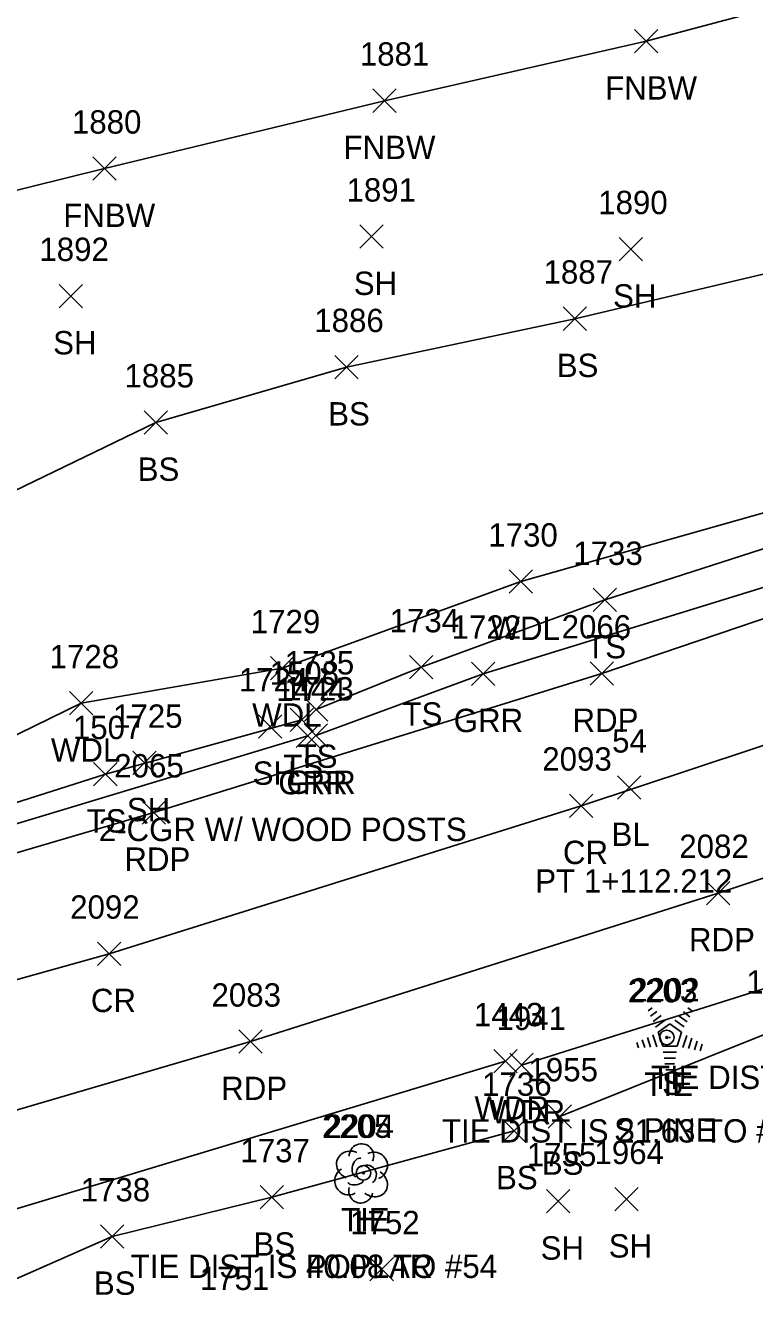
# Model space of a CAD drawing. Extents: x 1526508 to 1531550, y 369926 to 373082.
# Drawn here: x 1531169.1 to 1531231.6, y 370143.1 to 370252.3 of the extents above; entities that cross this region are included whole.
import ezdxf

# ---------------------------------------------------------------- set-up
doc = ezdxf.new("R2010")
doc.units = 0
for name, color, linetype in [('C_A', 7, 'Continuous'), ('C_C', 7, 'Continuous'), ('C_I', 7, 'Continuous'), ('C_TIC', 7, 'Continuous'), ('CBP', 7, 'Continuous'), ('L_A', 7, 'Continuous'), ('L_C', 7, 'Continuous'), ('L_I', 7, 'Continuous'), ('L_TIC', 7, 'Continuous'), ('LAWA', 7, 'Continuous'), ('LELB', 7, 'Continuous'), ('LFNC', 7, 'Continuous'), ('LTC', 7, 'Continuous'), ('LTD', 7, 'Continuous'), ('P_A', 7, 'Continuous'), ('P_I', 7, 'Continuous'), ('P_TIC', 7, 'Continuous'), ('PET', 7, 'Continuous'), ('PRC', 7, 'Continuous'), ('R_A', 7, 'Continuous'), ('R_C', 7, 'Continuous'), ('R_I', 7, 'Continuous'), ('R_TIC', 7, 'Continuous'), ('RGR', 7, 'Continuous')]:
    doc.layers.add(name, color=color, linetype=linetype)

msp = doc.modelspace()

# ---------------------------------------------------------------- linework, layer by layer
at = {"layer": 'C_TIC'}
for points in [[(1531219.82, 370186.04), (1531221.82, 370188.04)], [(1531221.82, 370186.04), (1531219.82, 370188.04)]]:
    msp.add_lwpolyline(points, dxfattribs=at)
at = {"layer": 'CBP'}
for centre, radius in [((1531224.04, 370165.64), 0.625), ((1531224.04, 370165.64), 0.0833), ((1531198.07, 370154.04), 0.625), ((1531198.07, 370154.04), 0.0833)]:
    msp.add_circle(centre, radius, dxfattribs=at)
at = {"layer": 'L_TIC'}
for points in [[(1531221.28, 370249.96), (1531223.28, 370251.96)], [(1531223.28, 370249.96), (1531221.28, 370251.96)], [(1531198.88, 370244.87), (1531200.88, 370246.87)], [(1531200.88, 370244.87), (1531198.88, 370246.87)], [(1531174.89, 370239.05), (1531176.89, 370241.05)], [(1531176.89, 370239.05), (1531174.89, 370241.05)], [(1531197.75, 370233.23), (1531199.75, 370235.23)], [(1531199.75, 370233.23), (1531197.75, 370235.23)], [(1531219.95, 370232.15), (1531221.95, 370234.15)], [(1531221.95, 370232.15), (1531219.95, 370234.15)], [(1531172.01, 370228.14), (1531174.01, 370230.14)], [(1531174.01, 370228.14), (1531172.01, 370230.14)], [(1531215.18, 370226.2), (1531217.18, 370228.2)], [(1531217.18, 370226.2), (1531215.18, 370228.2)], [(1531195.61, 370222.05), (1531197.61, 370224.05)], [(1531197.61, 370222.05), (1531195.61, 370224.05)], [(1531179.3, 370217.31), (1531181.3, 370219.31)], [(1531181.3, 370217.31), (1531179.3, 370219.31)], [(1531210.54, 370203.68), (1531212.54, 370205.68)], [(1531212.54, 370203.68), (1531210.54, 370205.68)], [(1531217.73, 370202.11), (1531219.73, 370204.11)], [(1531219.73, 370202.11), (1531217.73, 370204.11)], [(1531190.12, 370196.26), (1531192.12, 370198.26)], [(1531192.12, 370196.26), (1531190.12, 370198.26)], [(1531202, 370196.34), (1531204, 370198.34)], [(1531204, 370196.34), (1531202, 370198.34)], [(1531172.89, 370193.26), (1531174.89, 370195.26)], [(1531174.89, 370193.26), (1531172.89, 370195.26)], [(1531193.02, 370192.73), (1531195.02, 370194.73)], [(1531195.02, 370192.73), (1531193.02, 370194.73)], [(1531189.09, 370191.28), (1531191.09, 370193.28)], [(1531191.09, 370191.28), (1531189.09, 370193.28)], [(1531191.8, 370191.85), (1531193.8, 370193.85)], [(1531193.8, 370191.85), (1531191.8, 370193.85)], [(1531178.32, 370188.16), (1531180.32, 370190.16)], [(1531180.32, 370188.16), (1531178.32, 370190.16)], [(1531174.97, 370187.19), (1531176.97, 370189.19)], [(1531176.97, 370187.19), (1531174.97, 370189.19)], [(1531209.22, 370162.6), (1531211.22, 370164.6)], [(1531211.22, 370162.6), (1531209.22, 370164.6)], [(1531210.59, 370162.28), (1531212.59, 370164.28)], [(1531212.59, 370162.28), (1531210.59, 370164.28)], [(1531213.89, 370157.88), (1531215.89, 370159.88)], [(1531215.89, 370157.88), (1531213.89, 370159.88)], [(1531209.97, 370156.64), (1531211.97, 370158.64)], [(1531211.97, 370156.64), (1531209.97, 370158.64)], [(1531189.22, 370150.95), (1531191.22, 370152.95)], [(1531191.22, 370150.95), (1531189.22, 370152.95)], [(1531219.59, 370150.79), (1531221.59, 370152.79)], [(1531221.59, 370150.79), (1531219.59, 370152.79)], [(1531213.75, 370150.61), (1531215.75, 370152.61)], [(1531215.75, 370150.61), (1531213.75, 370152.61)], [(1531175.55, 370147.6), (1531177.55, 370149.6)], [(1531177.55, 370147.6), (1531175.55, 370149.6)], [(1531198.63, 370144.79), (1531200.63, 370146.79)], [(1531200.63, 370144.79), (1531198.63, 370146.79)]]:
    msp.add_lwpolyline(points, dxfattribs=at)
at = {"layer": 'LAWA'}
for points in [[(1531211.59, 370163.28), (1531236.15, 370171.01), (1531264.86, 370180.38), (1531296.6, 370192.07), (1531327.62, 370201.99), (1531350.93, 370208.46), (1531364.52, 370214)], [(1531159.07, 370187.01), (1531173.89, 370194.26), (1531191.12, 370197.26), (1531211.54, 370204.68), (1531235.67, 370211.51)], [(1531110.36, 370111.61), (1531088.81, 370117.3), (1531064.64, 370118.26), (1531064.75, 370123.38), (1531085.74, 370129.03), (1531112.09, 370135.21), (1531155.65, 370147.14), (1531210.22, 370163.6)]]:
    msp.add_lwpolyline(points, dxfattribs=at)
at = {"layer": 'LELB'}
for points in [[(1531144.65, 370206.06), (1531164.57, 370210.72), (1531180.3, 370218.31), (1531196.61, 370223.05), (1531216.18, 370227.2), (1531246.26, 370234.32), (1531259.5, 370237.9), (1531291.92, 370247.44), (1531321.67, 370253.97), (1531341.88, 370260.29), (1531377.42, 370272.37), (1531403.24, 370281.83), (1531425.1, 370287.02), (1531443.59, 370293.1), (1531470.33, 370300.31), (1531494.61, 370309.28), (1531517.9, 370316.82)], [(1531236.29, 370208.78), (1531218.73, 370203.11), (1531203, 370197.34), (1531194.02, 370193.73)], [(1531052, 370157.05), (1531071.33, 370161.04), (1531088.5, 370164.53), (1531103.99, 370168.65), (1531126.82, 370174.37), (1531147.94, 370179.24), (1531175.97, 370188.19), (1531192.8, 370192.85)], [(1531214.89, 370158.88), (1531233.6, 370166.39), (1531254.7, 370173.47), (1531274.83, 370179.73), (1531289.17, 370185.62), (1531304.59, 370187.71)], [(1531210.97, 370157.64), (1531190.22, 370151.95), (1531176.55, 370148.6), (1531161.06, 370141.76), (1531149.58, 370137.75), (1531135.28, 370131.25)]]:
    msp.add_lwpolyline(points, dxfattribs=at)
at = {"layer": 'LFNC'}
msp.add_lwpolyline([(1531134.08, 370228.63), (1531150.19, 370233.69), (1531175.89, 370240.05), (1531199.88, 370245.87), (1531222.28, 370250.96), (1531238.05, 370255.18), (1531253.57, 370259.14), (1531283.27, 370267), (1531318.04, 370276.03), (1531340.6, 370281.65), (1531362.15, 370285.77), (1531399.51, 370294.39), (1531422.47, 370298.84)], dxfattribs=at)
at = {"layer": 'LTC'}
for p, q in [((1531222.45, 370167.93), (1531222.8, 370168.19)), ((1531225.85, 370168.17), (1531226.27, 370167.87)), ((1531222.66, 370167.46), (1531223.19, 370167.85)), ((1531222.87, 370167), (1531223.57, 370167.51)), ((1531223.08, 370166.53), (1531223.95, 370167.17)), ((1531224.73, 370167.13), (1531225.54, 370166.54)), ((1531225.1, 370167.47), (1531225.78, 370166.98)), ((1531225.47, 370167.82), (1531226.02, 370167.42)), ((1531222.85, 370165.86), (1531223.18, 370164.84)), ((1531223.3, 370166.08), (1531224.31, 370166.81)), ((1531223.3, 370166.08), (1531223.69, 370164.88)), ((1531224.31, 370166.81), (1531225.31, 370166.09)), ((1531225.31, 370166.09), (1531224.92, 370164.88)), ((1531221.48, 370165.21), (1531221.63, 370164.74)), ((1531221.94, 370165.43), (1531222.15, 370164.77)), ((1531222.39, 370165.64), (1531222.66, 370164.81)), ((1531224.92, 370164.88), (1531223.69, 370164.88)), ((1531225.75, 370165.82), (1531225.41, 370164.78)), ((1531226.19, 370165.57), (1531225.9, 370164.68)), ((1531226.64, 370165.32), (1531226.4, 370164.59)), ((1531227.08, 370165.07), (1531226.89, 370164.49)), ((1531224.88, 370164.38), (1531223.74, 370164.38)), ((1531224.8, 370163.88), (1531223.81, 370163.88)), ((1531224.71, 370163.38), (1531223.88, 370163.38)), ((1531224.63, 370162.88), (1531223.95, 370162.88))]:
    msp.add_line(p, q, dxfattribs=at)
at = {"layer": 'LTD'}
msp.add_line((1531197.85, 370154.04), (1531197.85, 370154.04), dxfattribs=at)
msp.add_line((1531197.85, 370154.04), (1531197.85, 370154.04), dxfattribs=at)
msp.add_arc((1531197.9, 370155.48), 1.05, 335.5272, 180.9563, dxfattribs=at)
for centre, major_axis, ratio, start_param, end_param in [((1531197.06, 370154.71), (1.21, -0.51), 0.895232, 1.570796, 4.712389), ((1531197.65, 370154.5), (-0.208, -0.792), 0.645439, 3.141593, 6.283185), ((1531198.9, 370154.63), (-1.14, -0.48), 0.949671, 1.570796, 4.712389), ((1531196.77, 370153.33), (0.58, -1.04), 0.959034, 3.141593, 6.283185), ((1531198.35, 370153.88), (-0.5, 0.667), 0.989748, 3.141593, 6.283185), ((1531198.85, 370153.21), (-1.09, 0.79), 0.841452, 1.570796, 4.712389), ((1531197.85, 370152.54), (0.26, 1.06), 0.942809, 1.570796, 4.712389), ((1531197.4, 370153.29), (-0.625, -0.083), 0.423636, 0, 3.141593)]:
    msp.add_ellipse(centre, major_axis=major_axis, ratio=ratio, start_param=start_param, end_param=end_param, dxfattribs=at)
at = {"layer": 'P_TIC'}
for points in [[(1531217.48, 370195.81), (1531219.48, 370197.81)], [(1531219.48, 370195.81), (1531217.48, 370197.81)], [(1531179.11, 370183.91), (1531181.11, 370185.91)], [(1531181.11, 370183.91), (1531179.11, 370185.91)], [(1531215.72, 370184.49), (1531217.72, 370186.49)], [(1531217.72, 370184.49), (1531215.72, 370186.49)], [(1531227.45, 370177.01), (1531229.45, 370179.01)], [(1531229.45, 370177.01), (1531227.45, 370179.01)], [(1531175.3, 370171.81), (1531177.3, 370173.81)], [(1531177.3, 370171.81), (1531175.3, 370173.81)], [(1531187.4, 370164.28), (1531189.4, 370166.28)], [(1531189.4, 370164.28), (1531187.4, 370166.28)]]:
    msp.add_lwpolyline(points, dxfattribs=at)
at = {"layer": 'PET'}
for points in [[(1531036.19, 370150.91), (1531061.97, 370155.43), (1531104.8, 370164.58), (1531143.1, 370174.02), (1531180.11, 370184.91), (1531218.48, 370196.81), (1531260.06, 370210.9), (1531302.03, 370225.36), (1531352.57, 370243.2), (1531401.62, 370260.1), (1531448.12, 370277.05), (1531486.93, 370290.59), (1531531.91, 370306.21)], [(1531538.54, 370286.02), (1531506.28, 370274.48), (1531462.76, 370259.55), (1531429.61, 370248.08), (1531393.11, 370234.63), (1531350.62, 370219.92), (1531310.67, 370205.95), (1531271.31, 370192.3), (1531228.45, 370178.01), (1531188.4, 370165.28), (1531155.96, 370155.78), (1531116.2, 370145.37), (1531081.97, 370137.61), (1531057.06, 370132.93), (1531039.15, 370130.45)]]:
    msp.add_lwpolyline(points, dxfattribs=at)
at = {"layer": 'PRC'}
msp.add_lwpolyline([(1531037.76, 370140.53), (1531081.39, 370148.17), (1531130.61, 370160.04), (1531176.3, 370172.81), (1531216.72, 370185.49), (1531265.37, 370201.61), (1531315.14, 370219.14), (1531364.47, 370236.54), (1531403.01, 370250.24), (1531441.26, 370263.86), (1531484.78, 370279.08), (1531519.83, 370291.48), (1531535.78, 370296.89)], dxfattribs=at)
at = {"layer": 'R_TIC'}
for points in [[(1531207.31, 370195.79), (1531209.31, 370197.79)], [(1531209.31, 370195.79), (1531207.31, 370197.79)], [(1531192.3, 370190.46), (1531194.3, 370192.46)], [(1531194.3, 370190.46), (1531192.3, 370192.46)], [(1531192.99, 370190.5), (1531194.99, 370192.5)], [(1531194.99, 370190.5), (1531192.99, 370192.5)]]:
    msp.add_lwpolyline(points, dxfattribs=at)
at = {"layer": 'RGR'}
for points in [[(1531237.38, 370205.74), (1531208.31, 370196.79), (1531193.99, 370191.5)], [(1531193.3, 370191.46), (1531163.03, 370182.34), (1531135.13, 370174.16), (1531103.13, 370167.28), (1531088.75, 370162.91), (1531056.08, 370156.26)]]:
    msp.add_lwpolyline(points, dxfattribs=at)

# ---------------------------------------------------------------- texts
at = {"layer": 'C_A'}
for s, p in [('BL', (1531219.31, 370182.04)), ('TIE', (1531222.12, 370160.64)), ('TIE', (1531196.15, 370149.04))]:
    msp.add_text(s, height=2, dxfattribs=at).set_placement(p)
at = {"layer": 'C_C'}
for s, p in [('PT 1+112.212', (1531212.78, 370178.04)), ('TIE DIST IS 8.347 TO #54', (1531222.68, 370161.23)), ('TIE DIST IS 21.63 TO #54', (1531204.79, 370156.64)), ('TIE DIST IS 40.08 TO #54', (1531178.15, 370145.04))]:
    msp.add_text(s, height=2, dxfattribs=at).set_placement(p)
at = {"layer": 'C_I'}
for s, p in [('54', (1531219.36, 370190.04)), ('2203', (1531220.7, 370168.64)), ('2204', (1531194.74, 370157.04))]:
    msp.add_text(s, height=2, dxfattribs=at).set_placement(p)
at = {"layer": 'L_A'}
for s, p in [('FNBW', (1531218.76, 370245.96)), ('FNBW', (1531196.36, 370240.87)), ('FNBW', (1531172.37, 370235.05)), ('SH', (1531197.24, 370229.23)), ('SH', (1531219.44, 370228.15)), ('SH', (1531171.5, 370224.14)), ('BS', (1531214.62, 370222.2)), ('BS', (1531195.05, 370218.05)), ('BS', (1531178.74, 370213.31)), ('WDL', (1531208.95, 370199.68)), ('TS', (1531217.14, 370198.11)), ('WDL', (1531188.54, 370192.26)), ('TS', (1531201.41, 370192.34)), ('WDL', (1531171.31, 370189.26)), ('TS', (1531191.21, 370187.85)), ('TS', (1531192.43, 370188.73)), ('SH', (1531188.58, 370187.28)), ('SH', (1531177.81, 370184.16)), ('TS', (1531174.37, 370183.19)), ('S', (1531223.64, 370160.72)), ('WDR', (1531207.58, 370158.6)), ('WDR', (1531208.95, 370158.28)), ('BS', (1531213.34, 370153.88)), ('BS', (1531209.42, 370152.64)), ('H', (1531197.29, 370149.04)), ('BS', (1531188.66, 370146.95)), ('SH', (1531213.24, 370146.61)), ('SH', (1531219.07, 370146.79)), ('BS', (1531174.99, 370143.6))]:
    msp.add_text(s, height=2, dxfattribs=at).set_placement(p)
at = {"layer": 'L_C'}
for s, p in [('S PINE', (1531219.53, 370156.72)), ('S POPLAR', (1531190.6, 370145.04))]:
    msp.add_text(s, height=2, dxfattribs=at).set_placement(p)
at = {"layer": 'L_I'}
for s, p in [('1881', (1531197.76, 370248.87)), ('1880', (1531173.11, 370243.05)), ('1891', (1531196.62, 370237.23)), ('1890', (1531218.17, 370236.15)), ('1892', (1531170.32, 370232.14)), ('1887', (1531213.49, 370230.2)), ('1886', (1531193.86, 370226.05)), ('1885', (1531177.61, 370221.31)), ('1730', (1531208.76, 370207.68)), ('1733', (1531216.03, 370206.11)), ('1729', (1531188.42, 370200.26)), ('1734', (1531200.31, 370200.34)), ('1728', (1531171.2, 370197.26)), ('1735', (1531191.33, 370196.73)), ('1508', (1531190.03, 370195.85)), ('1724', (1531187.4, 370195.28)), ('1507', (1531173.19, 370191.19)), ('1725', (1531176.63, 370192.16)), ('1956', (1531230.85, 370169.39)), ('2202', (1531220.91, 370168.72)), ('1443', (1531207.53, 370166.6)), ('1941', (1531209.46, 370166.28)), ('1955', (1531212.2, 370161.88)), ('1736', (1531208.23, 370160.64)), ('2205', (1531194.52, 370157.04)), ('1737', (1531187.53, 370154.95)), ('1755', (1531212.06, 370154.61)), ('1964', (1531217.85, 370154.79)), ('1738', (1531173.86, 370151.6)), ('1752', (1531196.93, 370148.79)), ('1751', (1531184.06, 370144.01))]:
    msp.add_text(s, height=2, dxfattribs=at).set_placement(p)
at = {"layer": 'LTC'}
msp.add_text('.', height=1.04, rotation=270, dxfattribs=at).set_placement((1531224.2, 370165.83))
at = {"layer": 'P_A'}
for s, p in [('RDP', (1531215.97, 370191.81)), ('CR', (1531215.15, 370180.49)), ('RDP', (1531177.6, 370179.91)), ('RDP', (1531225.94, 370173.01)), ('CR', (1531174.73, 370167.81)), ('RDP', (1531185.89, 370160.28))]:
    msp.add_text(s, height=2, dxfattribs=at).set_placement(p)
at = {"layer": 'P_I'}
for s, p in [('2066', (1531215.04, 370199.81)), ('2065', (1531176.73, 370187.91)), ('2093', (1531213.38, 370188.49)), ('2082', (1531225.11, 370181.01)), ('2092', (1531172.96, 370175.81)), ('2083', (1531185.06, 370168.28))]:
    msp.add_text(s, height=2, dxfattribs=at).set_placement(p)
at = {"layer": 'R_A'}
for p in [(1531205.8, 370191.79), (1531190.78, 370186.46), (1531191.47, 370186.5)]:
    msp.add_text('GRR', height=2, dxfattribs=at).set_placement(p)
at = {"layer": 'R_C'}
msp.add_text('2-CGR W/ WOOD POSTS', height=2, dxfattribs=at).set_placement((1531175.41, 370182.46))
at = {"layer": 'R_I'}
for s, p in [('1722', (1531205.62, 370199.79)), ('1444', (1531190.6, 370194.46)), ('1723', (1531191.29, 370194.5))]:
    msp.add_text(s, height=2, dxfattribs=at).set_placement(p)

doc.saveas('drawing.dxf')
